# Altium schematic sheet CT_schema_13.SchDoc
size 387 x 385 mm
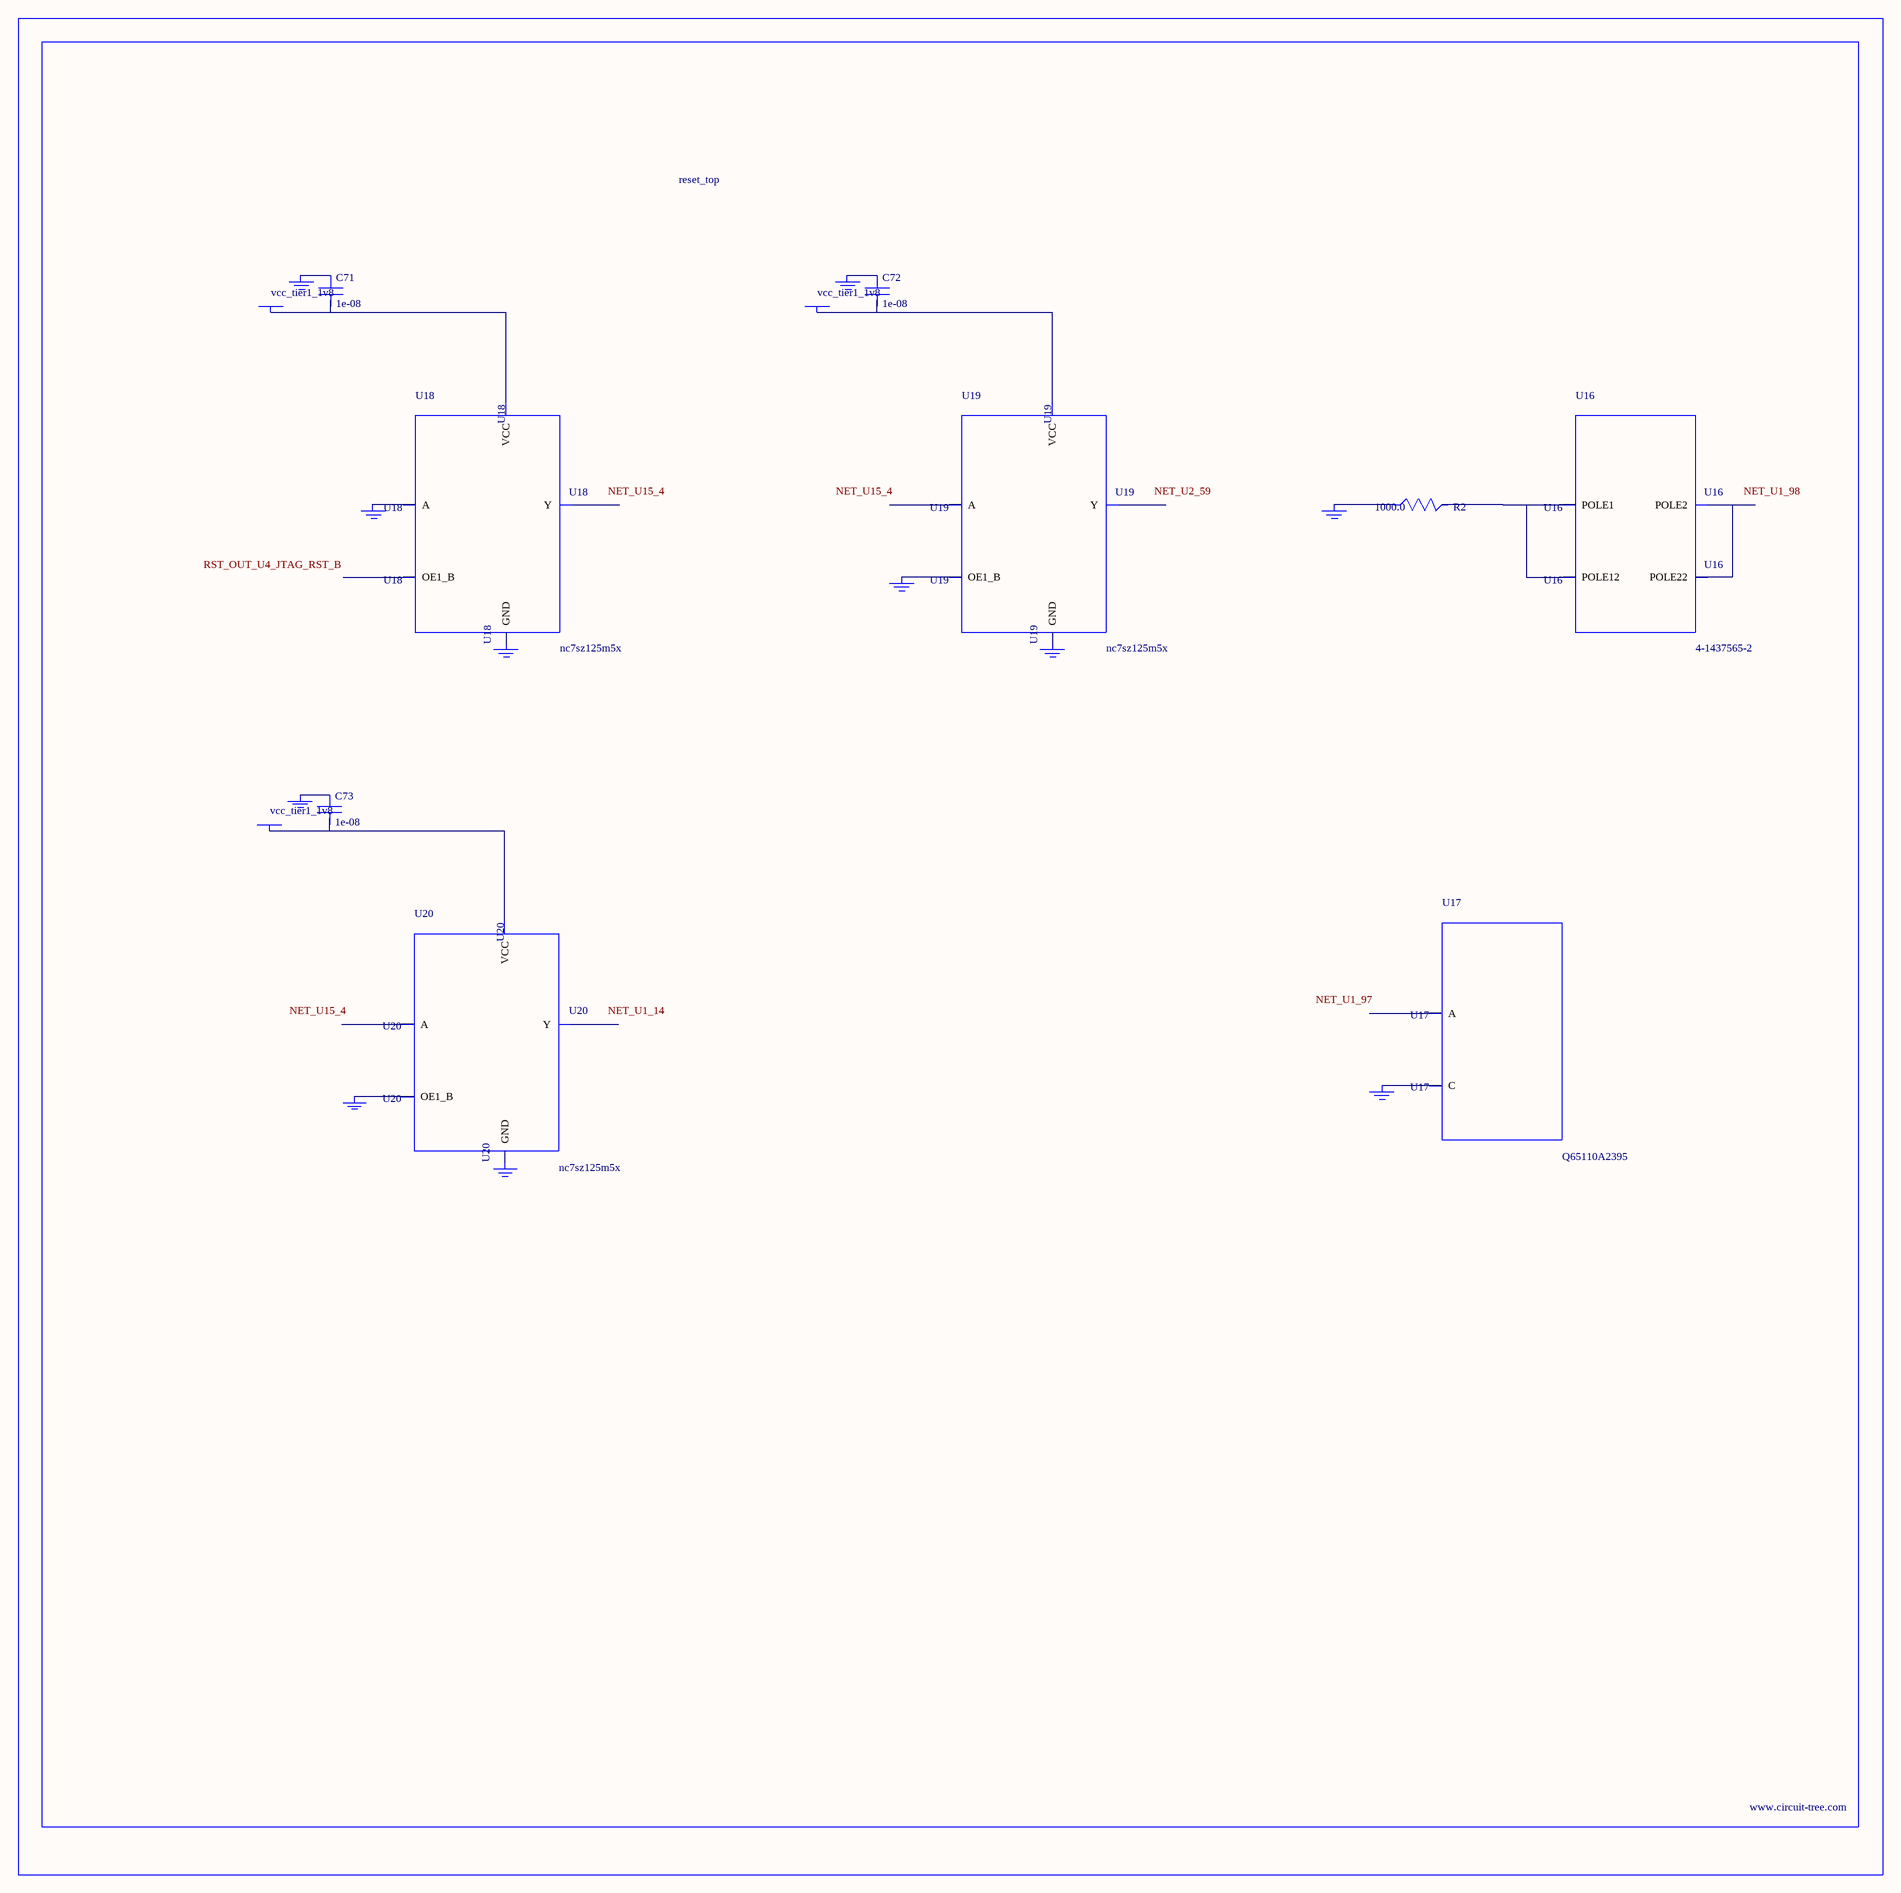
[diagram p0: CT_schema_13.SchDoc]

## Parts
BORDER12  (no value)
C71  1e-08  [C0402]
C72  1e-08  [C0402]
C73  1e-08  [C0402]
GND_INSTANCE_12_0  (no value)
GND_INSTANCE_12_1  (no value)
GND_INSTANCE_12_2  (no value)
GND_INSTANCE_12_3  (no value)
GND_INSTANCE_12_4  (no value)
GND_INSTANCE_12_5  (no value)
GND_INSTANCE_12_6  (no value)
GND_INSTANCE_12_7  (no value)
GND_INSTANCE_12_8  (no value)
GND_INSTANCE_12_9  (no value)
GND_INSTANCE_12_10  (no value)
POWER_INSTANCE_12_0  vcc_tier1_1v8
POWER_INSTANCE_12_1  vcc_tier1_1v8
POWER_INSTANCE_12_2  vcc_tier1_1v8
R2  1000.0  [R0603]
U16  4-1437565-2  [SW_4-1437565-2]
U17  Q65110A2395  [LGM67K-G1J2-24-Z]
U18  nc7sz125m5x  [NC7SZ125M5X]
U19  nc7sz125m5x  [NC7SZ125M5X]
U20  nc7sz125m5x  [NC7SZ125M5X]

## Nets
NetC71_1: C71.1 GND_INSTANCE_12_2.0(GND)
NetC71_2: C71.2 POWER_INSTANCE_12_0.0(PWR) U18.5(VCC)
NetC72_1: C72.1 GND_INSTANCE_12_5.0(GND)
NetC72_2: C72.2 POWER_INSTANCE_12_1.0(PWR) U19.5(VCC)
NetC73_1: C73.1 GND_INSTANCE_12_8.0(GND)
NetC73_2: C73.2 POWER_INSTANCE_12_2.0(PWR) U20.5(VCC)
NetGND_INSTANCE_12_0_0: GND_INSTANCE_12_0.0(GND) R2.1
NetGND_INSTANCE_12_1_0: GND_INSTANCE_12_1.0(GND) U17.C
NetGND_INSTANCE_12_3_0: GND_INSTANCE_12_3.0(GND) U18.2(A)
NetGND_INSTANCE_12_4_0: GND_INSTANCE_12_4.0(GND) U18.3(GND)
NetGND_INSTANCE_12_6_0: GND_INSTANCE_12_6.0(GND) U19.1(OE1_B)
NetGND_INSTANCE_12_7_0: GND_INSTANCE_12_7.0(GND) U19.3(GND)
NetGND_INSTANCE_12_9_0: GND_INSTANCE_12_9.0(GND) U20.1(OE1_B)
NetGND_INSTANCE_12_10_0: GND_INSTANCE_12_10.0(GND) U20.3(GND)
NetR2_2: R2.2 U16.1(POLE1) U16.2(POLE12)
NetU16_3: U16.3(POLE2) U16.4(POLE22)

Not connected (* = marked no-connect by the designer): U17 A; U18 1(OE1_B) 4(Y); U19 2(A) 4(Y); U20 2(A) 4(Y)

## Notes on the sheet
- Labels drawn without touching a wire or pin: NET_U1_14, NET_U1_97, NET_U1_98, NET_U2_59, NET_U15_4, RST_OUT_U4_JTAG_RST_B

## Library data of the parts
BORDER12 = BORDER_PAGE12
C71-C73 = C0402C103K3RAC
GND_INSTANCE_12_0-GND_INSTANCE_12_10 = GND
POWER_INSTANCE_12_0-POWER_INSTANCE_12_2 = PWR
R2 = RC0603JR-071KL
